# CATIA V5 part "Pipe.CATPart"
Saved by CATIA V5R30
Part number: Pipe
Bounding box of the stored display mesh (mm): x -50 to 50, y 0 to 150, z -50 to 50
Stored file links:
  D:\PROJECTS\CATIA V56R 2020\Resources\Parts File\c12_catia_v5_6r2020_prt\c12_catia_v5-6r2020 figr_12-39\Pipe.CATPart
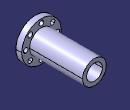
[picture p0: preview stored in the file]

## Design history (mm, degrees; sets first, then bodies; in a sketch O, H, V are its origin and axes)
Body1 (main body)
  Sketch1 on zx-plane, origin (0, 0, 0), H (-1, 0, 0), V (0, 0, 1)
    circle A1 centre (0, 0) radius 50
    point P1 (0, -50)
    circle A2 centre (0, 0) radius 30
    point P2 (0, -30)
    radius A1 = 50
    radius A2 = 30
    coincidence: A1 P1, P1 V, A2 P2, P2 V
  MultiPad1: profile Sketch1, domains (length 150; length 15)
  Sketch2 on face of MultiPad1, origin (0, 150, 0), H (-1, 0, 0), V (0, 0, 1)
    circle A1 centre (0, 0) radius 20
    point P1 (0, -20)
    radius A1 = 20
    coincidence: A1 P1, P1 V
  Pocket1: profile Sketch2, direction (0, -1, 0), through (limit type 3)
  Sketch3 on face of MultiPad1, origin (0, 0, 0), H (1, 0, 0), V (0, 0, 1)
    circle A1 centre (0, -40) radius 6
    point P1 (0, -40)
    radius A1 = 6
    distance H P1 = 40
    coincidence: P1 V
  Pocket2: profile Sketch3, direction (0, 1, 0), through (limit type 3)
  CircPattern1: of Pocket2, instances 8, angular step 45, axis from face of MultiPad1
